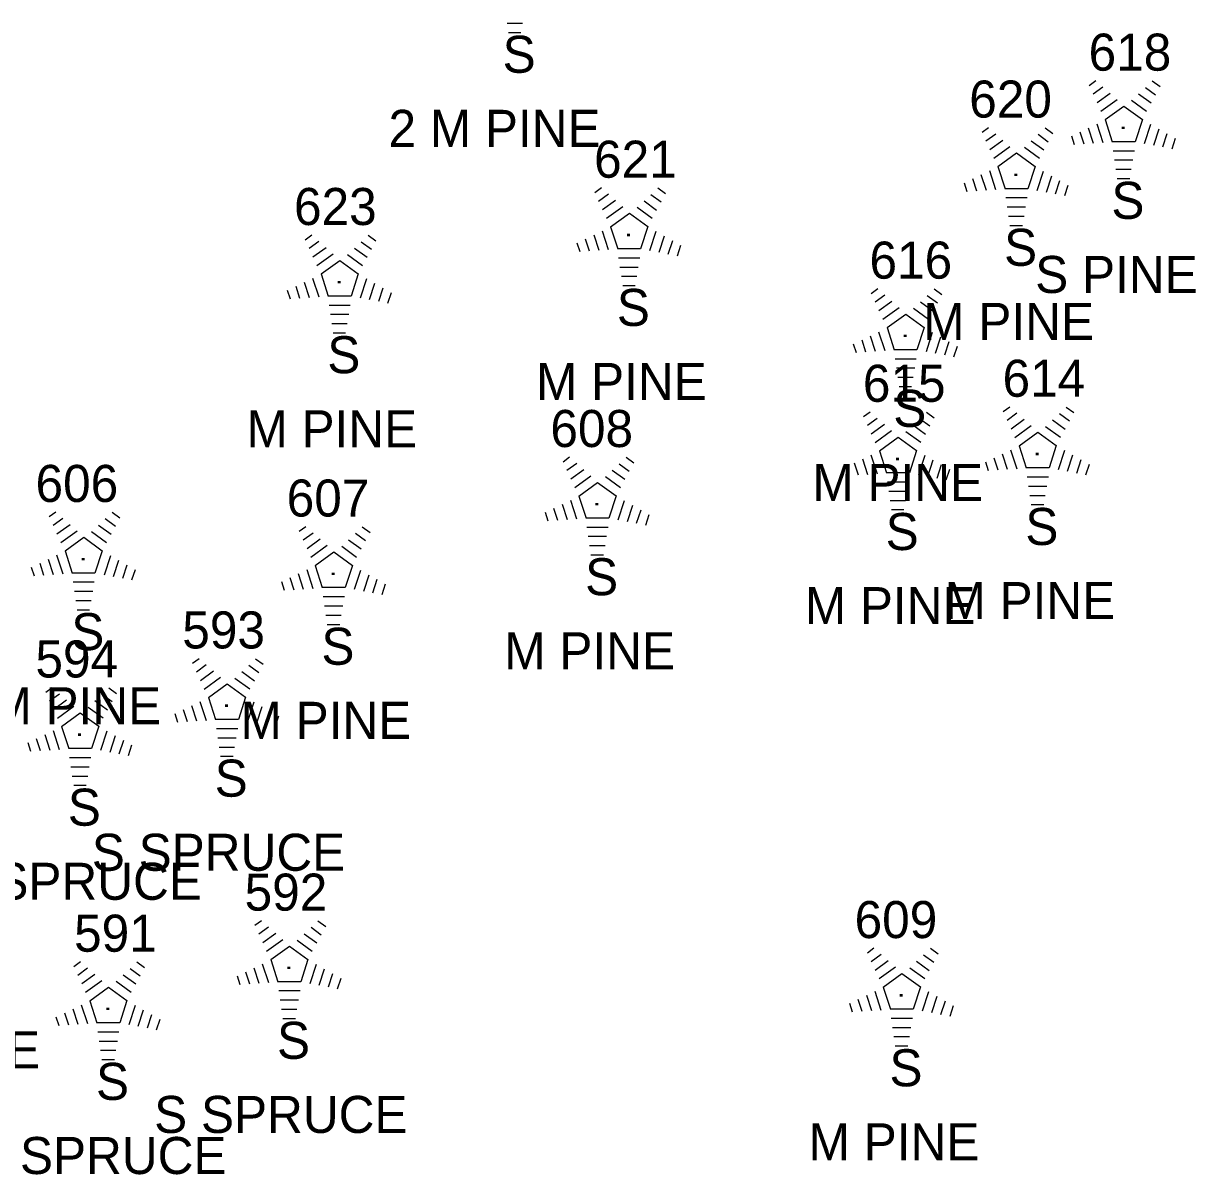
# Model space of a CAD drawing. Extents: x 1545627 to 1546562, y 571176 to 576667.
# Drawn here: x 1546217.9 to 1546281.1, y 572043.8 to 572106 of the extents above; entities that cross this region are included whole.
import ezdxf

# ---------------------------------------------------------------- set-up
doc = ezdxf.new("R2010")
doc.units = 0
for name, color, linetype in [('L_A', 7, 'Continuous'), ('L_C', 7, 'Continuous'), ('L_I', 7, 'Continuous'), ('LTC', 7, 'Continuous')]:
    doc.layers.add(name, color=color, linetype=linetype)

msp = doc.modelspace()

# ---------------------------------------------------------------- linework, layer by layer
at = {"layer": 'LTC'}
for p, q in [((1546244.786, 572105.976), (1546243.955, 572105.976)), ((1546244.703, 572105.476), (1546244.028, 572105.476)), ((1546275.376, 572102.634), (1546275.731, 572102.891)), ((1546275.586, 572102.168), (1546276.115, 572102.553)), ((1546278.403, 572102.526), (1546278.953, 572102.127)), ((1546278.774, 572102.874), (1546279.193, 572102.57)), ((1546275.795, 572101.703), (1546276.499, 572102.214)), ((1546276.005, 572101.237), (1546276.883, 572101.875)), ((1546277.661, 572101.829), (1546278.471, 572101.241)), ((1546278.032, 572102.178), (1546278.711, 572101.684)), ((1546276.229, 572100.782), (1546277.241, 572101.516)), ((1546277.241, 572101.516), (1546278.238, 572100.791)), ((1546275.775, 572100.563), (1546276.106, 572099.543)), ((1546276.229, 572100.782), (1546276.616, 572099.588)), ((1546278.238, 572100.791), (1546277.847, 572099.588)), ((1546269.587, 572100.101), (1546269.942, 572100.359)), ((1546269.797, 572099.636), (1546270.326, 572100.02)), ((1546272.614, 572099.993), (1546273.164, 572099.594)), ((1546272.985, 572100.342), (1546273.404, 572100.037)), ((1546274.408, 572099.913), (1546274.561, 572099.445)), ((1546274.864, 572100.13), (1546275.076, 572099.478)), ((1546275.319, 572100.346), (1546275.591, 572099.511)), ((1546278.676, 572100.521), (1546278.338, 572099.481)), ((1546279.12, 572100.27), (1546278.833, 572099.386)), ((1546279.565, 572100.02), (1546279.328, 572099.291)), ((1546270.006, 572099.17), (1546270.71, 572099.681)), ((1546270.216, 572098.704), (1546271.094, 572099.342)), ((1546271.872, 572099.297), (1546272.682, 572098.708)), ((1546272.243, 572099.645), (1546272.922, 572099.151)), ((1546277.847, 572099.588), (1546276.616, 572099.588)), ((1546280.009, 572099.77), (1546279.822, 572099.196)), ((1546270.44, 572098.249), (1546271.452, 572098.984)), ((1546271.452, 572098.984), (1546272.449, 572098.259)), ((1546277.808, 572099.088), (1546276.664, 572099.088)), ((1546269.986, 572098.03), (1546270.317, 572097.011)), ((1546270.44, 572098.249), (1546270.827, 572097.056)), ((1546272.449, 572098.259), (1546272.058, 572097.056)), ((1546277.725, 572098.588), (1546276.736, 572098.588)), ((1546277.641, 572098.088), (1546276.809, 572098.088)), ((1546268.619, 572097.38), (1546268.772, 572096.912)), ((1546269.075, 572097.597), (1546269.287, 572096.945)), ((1546269.53, 572097.814), (1546269.802, 572096.978)), ((1546272.887, 572097.988), (1546272.549, 572096.948)), ((1546273.331, 572097.737), (1546273.044, 572096.853)), ((1546273.776, 572097.487), (1546273.539, 572096.758)), ((1546277.557, 572097.588), (1546276.882, 572097.588)), ((1546248.687, 572096.855), (1546249.041, 572097.113)), ((1546248.896, 572096.39), (1546249.425, 572096.774)), ((1546251.714, 572096.748), (1546252.263, 572096.348)), ((1546252.085, 572097.096), (1546252.504, 572096.791)), ((1546272.058, 572097.056), (1546270.827, 572097.056)), ((1546274.22, 572097.237), (1546274.033, 572096.663)), ((1546249.106, 572095.924), (1546249.81, 572096.435)), ((1546251.343, 572096.399), (1546252.022, 572095.905)), ((1546272.019, 572096.556), (1546270.875, 572096.556)), ((1546249.315, 572095.458), (1546250.194, 572096.096)), ((1546249.54, 572095.003), (1546250.552, 572095.738)), ((1546250.552, 572095.738), (1546251.549, 572095.013)), ((1546250.972, 572096.051), (1546251.781, 572095.462)), ((1546271.936, 572096.056), (1546270.947, 572096.056)), ((1546271.852, 572095.556), (1546271.02, 572095.556)), ((1546249.54, 572095.003), (1546249.927, 572093.81)), ((1546251.549, 572095.013), (1546251.158, 572093.81)), ((1546271.768, 572095.056), (1546271.093, 572095.056)), ((1546233.059, 572094.304), (1546233.414, 572094.561)), ((1546233.269, 572093.838), (1546233.798, 572094.222)), ((1546236.457, 572094.544), (1546236.877, 572094.239)), ((1546248.175, 572094.351), (1546248.386, 572093.7)), ((1546248.63, 572094.568), (1546248.901, 572093.733)), ((1546249.085, 572094.784), (1546249.416, 572093.765)), ((1546251.986, 572094.742), (1546251.648, 572093.703)), ((1546252.431, 572094.492), (1546252.143, 572093.607)), ((1546252.875, 572094.242), (1546252.638, 572093.512)), ((1546233.478, 572093.372), (1546234.182, 572093.884)), ((1546235.715, 572093.847), (1546236.395, 572093.354)), ((1546236.086, 572094.196), (1546236.636, 572093.797)), ((1546247.719, 572094.135), (1546247.871, 572093.667)), ((1546251.158, 572093.81), (1546249.927, 572093.81)), ((1546253.32, 572093.991), (1546253.133, 572093.417)), ((1546233.688, 572092.907), (1546234.566, 572093.544)), ((1546233.912, 572092.452), (1546234.924, 572093.186)), ((1546234.924, 572093.186), (1546235.921, 572092.461)), ((1546235.344, 572093.499), (1546236.154, 572092.91)), ((1546251.119, 572093.31), (1546249.975, 572093.31)), ((1546233.912, 572092.452), (1546234.3, 572091.258)), ((1546235.921, 572092.461), (1546235.53, 572091.258)), ((1546251.035, 572092.81), (1546250.047, 572092.81)), ((1546250.952, 572092.31), (1546250.12, 572092.31)), ((1546232.547, 572091.799), (1546232.759, 572091.148)), ((1546233.002, 572092.016), (1546233.274, 572091.181)), ((1546233.458, 572092.232), (1546233.789, 572091.213)), ((1546236.359, 572092.19), (1546236.021, 572091.151)), ((1546236.803, 572091.94), (1546236.516, 572091.055)), ((1546237.248, 572091.69), (1546237.011, 572090.96)), ((1546250.868, 572091.81), (1546250.193, 572091.81)), ((1546232.092, 572091.583), (1546232.244, 572091.115)), ((1546235.53, 572091.258), (1546234.3, 572091.258)), ((1546237.692, 572091.439), (1546237.505, 572090.865)), ((1546263.605, 572091.407), (1546263.959, 572091.664)), ((1546263.814, 572090.941), (1546264.343, 572091.326)), ((1546266.632, 572091.299), (1546267.181, 572090.9)), ((1546267.003, 572091.647), (1546267.422, 572091.343)), ((1546235.492, 572090.758), (1546234.347, 572090.758)), ((1546264.024, 572090.476), (1546264.727, 572090.987)), ((1546264.233, 572090.01), (1546265.112, 572090.648)), ((1546265.89, 572090.602), (1546266.699, 572090.014)), ((1546266.261, 572090.951), (1546266.94, 572090.457)), ((1546235.408, 572090.258), (1546234.42, 572090.258)), ((1546264.458, 572089.555), (1546265.47, 572090.289)), ((1546265.47, 572090.289), (1546266.467, 572089.564)), ((1546235.324, 572089.758), (1546234.492, 572089.758)), ((1546235.24, 572089.258), (1546234.565, 572089.258)), ((1546264.003, 572089.336), (1546264.334, 572088.316)), ((1546264.458, 572089.555), (1546264.845, 572088.361)), ((1546266.467, 572089.564), (1546266.075, 572088.361)), ((1546266.904, 572089.294), (1546266.566, 572088.254)), ((1546262.637, 572088.686), (1546262.789, 572088.218)), ((1546263.092, 572088.903), (1546263.304, 572088.251)), ((1546263.548, 572089.119), (1546263.819, 572088.284)), ((1546267.349, 572089.043), (1546267.061, 572088.159)), ((1546267.793, 572088.793), (1546267.556, 572088.064)), ((1546268.237, 572088.543), (1546268.051, 572087.969)), ((1546266.075, 572088.361), (1546264.845, 572088.361)), ((1546266.037, 572087.861), (1546264.892, 572087.861)), ((1546265.953, 572087.361), (1546264.965, 572087.361)), ((1546265.87, 572086.861), (1546265.038, 572086.861)), ((1546265.786, 572086.361), (1546265.111, 572086.361)), ((1546263.193, 572084.759), (1546263.548, 572085.017)), ((1546266.592, 572085), (1546267.011, 572084.695)), ((1546270.733, 572085.031), (1546271.087, 572085.288)), ((1546270.942, 572084.565), (1546271.471, 572084.949)), ((1546273.76, 572084.923), (1546274.309, 572084.524)), ((1546274.131, 572085.271), (1546274.55, 572084.967)), ((1546263.403, 572084.294), (1546263.932, 572084.678)), ((1546263.612, 572083.828), (1546264.316, 572084.339)), ((1546265.849, 572084.303), (1546266.529, 572083.809)), ((1546266.22, 572084.651), (1546266.77, 572084.252)), ((1546271.152, 572084.099), (1546271.856, 572084.611)), ((1546271.361, 572083.634), (1546272.24, 572084.272)), ((1546273.018, 572084.226), (1546273.827, 572083.637)), ((1546273.389, 572084.574), (1546274.068, 572084.081)), ((1546263.822, 572083.362), (1546264.7, 572084)), ((1546264.047, 572082.907), (1546265.058, 572083.642)), ((1546265.058, 572083.642), (1546266.055, 572082.917)), ((1546265.478, 572083.955), (1546266.288, 572083.366)), ((1546271.586, 572083.179), (1546272.598, 572083.913)), ((1546272.598, 572083.913), (1546273.595, 572083.188)), ((1546264.047, 572082.907), (1546264.434, 572081.714)), ((1546266.055, 572082.917), (1546265.664, 572081.714)), ((1546271.131, 572082.959), (1546271.462, 572081.94)), ((1546271.586, 572083.179), (1546271.973, 572081.985)), ((1546273.595, 572083.188), (1546273.204, 572081.985)), ((1546274.032, 572082.917), (1546273.694, 572081.878)), ((1546246.975, 572082.319), (1546247.329, 572082.576)), ((1546247.184, 572081.854), (1546247.713, 572082.238)), ((1546250.002, 572082.211), (1546250.551, 572081.812)), ((1546250.373, 572082.559), (1546250.792, 572082.255)), ((1546262.681, 572082.255), (1546262.893, 572081.603)), ((1546263.137, 572082.472), (1546263.408, 572081.636)), ((1546263.592, 572082.688), (1546263.923, 572081.669)), ((1546266.493, 572082.646), (1546266.155, 572081.606)), ((1546266.937, 572082.395), (1546266.65, 572081.511)), ((1546269.765, 572082.31), (1546269.917, 572081.842)), ((1546270.221, 572082.527), (1546270.432, 572081.875)), ((1546270.676, 572082.743), (1546270.947, 572081.908)), ((1546274.477, 572082.667), (1546274.189, 572081.782)), ((1546274.921, 572082.417), (1546274.684, 572081.687)), ((1546247.394, 572081.388), (1546248.098, 572081.899)), ((1546247.603, 572080.922), (1546248.482, 572081.56)), ((1546249.631, 572081.863), (1546250.31, 572081.369)), ((1546262.226, 572082.038), (1546262.378, 572081.57)), ((1546265.664, 572081.714), (1546264.434, 572081.714)), ((1546267.382, 572082.145), (1546267.145, 572081.416)), ((1546267.826, 572081.895), (1546267.639, 572081.321)), ((1546273.204, 572081.985), (1546271.973, 572081.985)), ((1546275.366, 572082.167), (1546275.179, 572081.592)), ((1546247.828, 572080.467), (1546248.84, 572081.201)), ((1546248.84, 572081.201), (1546249.837, 572080.476)), ((1546249.26, 572081.514), (1546250.069, 572080.926)), ((1546265.626, 572081.214), (1546264.481, 572081.214)), ((1546273.165, 572081.485), (1546272.021, 572081.485)), ((1546273.081, 572080.985), (1546272.093, 572080.985)), ((1546247.828, 572080.467), (1546248.215, 572079.274)), ((1546249.837, 572080.476), (1546249.445, 572079.274)), ((1546265.542, 572080.714), (1546264.554, 572080.714)), ((1546272.998, 572080.485), (1546272.166, 572080.485)), ((1546246.463, 572079.815), (1546246.674, 572079.163)), ((1546246.918, 572080.031), (1546247.189, 572079.196)), ((1546247.373, 572080.248), (1546247.704, 572079.229)), ((1546250.274, 572080.206), (1546249.936, 572079.166)), ((1546250.719, 572079.955), (1546250.431, 572079.071)), ((1546251.163, 572079.705), (1546250.926, 572078.976)), ((1546265.458, 572080.214), (1546264.627, 572080.214)), ((1546265.374, 572079.714), (1546264.699, 572079.714)), ((1546272.914, 572079.985), (1546272.239, 572079.985)), ((1546219.242, 572079.355), (1546219.597, 572079.612)), ((1546219.452, 572078.889), (1546219.981, 572079.274)), ((1546222.269, 572079.247), (1546222.819, 572078.848)), ((1546222.64, 572079.595), (1546223.06, 572079.291)), ((1546246.007, 572079.598), (1546246.159, 572079.13)), ((1546249.445, 572079.274), (1546248.215, 572079.274)), ((1546251.608, 572079.455), (1546251.421, 572078.881)), ((1546219.661, 572078.424), (1546220.365, 572078.935)), ((1546219.871, 572077.958), (1546220.749, 572078.596)), ((1546221.527, 572078.55), (1546222.337, 572077.962)), ((1546221.898, 572078.899), (1546222.578, 572078.405)), ((1546232.741, 572078.567), (1546233.095, 572078.824)), ((1546232.95, 572078.101), (1546233.48, 572078.485)), ((1546235.768, 572078.459), (1546236.318, 572078.059)), ((1546236.139, 572078.807), (1546236.558, 572078.502)), ((1546249.407, 572078.774), (1546248.263, 572078.774)), ((1546220.095, 572077.503), (1546221.107, 572078.237)), ((1546221.107, 572078.237), (1546222.104, 572077.512)), ((1546233.16, 572077.635), (1546233.864, 572078.147)), ((1546233.37, 572077.169), (1546234.248, 572077.807)), ((1546235.026, 572077.762), (1546235.835, 572077.173)), ((1546235.397, 572078.11), (1546236.076, 572077.617)), ((1546249.323, 572078.274), (1546248.335, 572078.274)), ((1546249.24, 572077.774), (1546248.408, 572077.774)), ((1546219.641, 572077.284), (1546219.972, 572076.264)), ((1546220.095, 572077.503), (1546220.483, 572076.309)), ((1546222.104, 572077.512), (1546221.713, 572076.309)), ((1546222.542, 572077.242), (1546222.204, 572076.202)), ((1546233.594, 572076.714), (1546234.606, 572077.449)), ((1546234.606, 572077.449), (1546235.603, 572076.724)), ((1546249.156, 572077.274), (1546248.481, 572077.274)), ((1546218.275, 572076.634), (1546218.427, 572076.166)), ((1546218.73, 572076.851), (1546218.942, 572076.199)), ((1546219.185, 572077.067), (1546219.457, 572076.232)), ((1546222.986, 572076.991), (1546222.699, 572076.107)), ((1546223.431, 572076.741), (1546223.194, 572076.012)), ((1546223.875, 572076.491), (1546223.688, 572075.917)), ((1546233.14, 572076.495), (1546233.47, 572075.476)), ((1546233.594, 572076.714), (1546233.981, 572075.521)), ((1546235.603, 572076.724), (1546235.212, 572075.521)), ((1546221.713, 572076.309), (1546220.483, 572076.309)), ((1546232.229, 572076.062), (1546232.44, 572075.411)), ((1546232.684, 572076.279), (1546232.955, 572075.444)), ((1546236.04, 572076.453), (1546235.703, 572075.414)), ((1546236.485, 572076.203), (1546236.198, 572075.318)), ((1546236.93, 572075.953), (1546236.693, 572075.223)), ((1546221.675, 572075.809), (1546220.53, 572075.809)), ((1546221.591, 572075.309), (1546220.603, 572075.309)), ((1546231.773, 572075.846), (1546231.925, 572075.378)), ((1546235.212, 572075.521), (1546233.981, 572075.521)), ((1546237.374, 572075.702), (1546237.187, 572075.128)), ((1546221.507, 572074.809), (1546220.675, 572074.809)), ((1546235.173, 572075.021), (1546234.029, 572075.021)), ((1546221.423, 572074.309), (1546220.748, 572074.309)), ((1546235.09, 572074.521), (1546234.101, 572074.521)), ((1546235.006, 572074.021), (1546234.174, 572074.021)), ((1546234.922, 572073.521), (1546234.247, 572073.521)), ((1546226.981, 572071.447), (1546227.335, 572071.704)), ((1546230.379, 572071.687), (1546230.798, 572071.382)), ((1546227.19, 572070.981), (1546227.72, 572071.365)), ((1546227.4, 572070.515), (1546228.104, 572071.027)), ((1546229.637, 572070.99), (1546230.316, 572070.497)), ((1546230.008, 572071.339), (1546230.558, 572070.94)), ((1546227.61, 572070.05), (1546228.488, 572070.687)), ((1546227.834, 572069.595), (1546228.846, 572070.329)), ((1546228.846, 572070.329), (1546229.843, 572069.604)), ((1546229.266, 572070.642), (1546230.075, 572070.053)), ((1546219.056, 572069.88), (1546219.41, 572070.137)), ((1546219.265, 572069.414), (1546219.795, 572069.798)), ((1546222.083, 572069.772), (1546222.633, 572069.372)), ((1546222.454, 572070.12), (1546222.873, 572069.815)), ((1546227.834, 572069.595), (1546228.221, 572068.401)), ((1546229.843, 572069.604), (1546229.452, 572068.401)), ((1546219.475, 572068.948), (1546220.179, 572069.46)), ((1546219.685, 572068.482), (1546220.563, 572069.12)), ((1546221.341, 572069.075), (1546222.15, 572068.486)), ((1546221.712, 572069.423), (1546222.391, 572068.93)), ((1546226.469, 572068.942), (1546226.68, 572068.291)), ((1546226.924, 572069.159), (1546227.195, 572068.324)), ((1546227.38, 572069.375), (1546227.71, 572068.356)), ((1546230.28, 572069.333), (1546229.943, 572068.294)), ((1546230.725, 572069.083), (1546230.438, 572068.198)), ((1546219.909, 572068.027), (1546220.921, 572068.762)), ((1546220.921, 572068.762), (1546221.918, 572068.037)), ((1546226.013, 572068.726), (1546226.165, 572068.258)), ((1546229.452, 572068.401), (1546228.221, 572068.401)), ((1546231.17, 572068.833), (1546230.933, 572068.103)), ((1546231.614, 572068.582), (1546231.427, 572068.008)), ((1546219.455, 572067.808), (1546219.785, 572066.789)), ((1546219.909, 572068.027), (1546220.296, 572066.834)), ((1546221.918, 572068.037), (1546221.527, 572066.834)), ((1546222.355, 572067.766), (1546222.018, 572066.727)), ((1546229.413, 572067.901), (1546228.269, 572067.901)), ((1546218.088, 572067.159), (1546218.24, 572066.691)), ((1546218.544, 572067.375), (1546218.755, 572066.724)), ((1546218.999, 572067.592), (1546219.27, 572066.757)), ((1546222.8, 572067.516), (1546222.513, 572066.631)), ((1546223.245, 572067.266), (1546223.008, 572066.536)), ((1546223.689, 572067.015), (1546223.502, 572066.441)), ((1546229.33, 572067.401), (1546228.341, 572067.401)), ((1546221.527, 572066.834), (1546220.296, 572066.834)), ((1546229.246, 572066.901), (1546228.414, 572066.901)), ((1546229.162, 572066.401), (1546228.487, 572066.401)), ((1546221.488, 572066.334), (1546220.344, 572066.334)), ((1546221.405, 572065.834), (1546220.416, 572065.834)), ((1546221.321, 572065.334), (1546220.489, 572065.334)), ((1546221.237, 572064.834), (1546220.562, 572064.834)), ((1546230.345, 572057.295), (1546230.7, 572057.552)), ((1546233.743, 572057.535), (1546234.163, 572057.23)), ((1546230.555, 572056.829), (1546231.084, 572057.213)), ((1546233.372, 572057.187), (1546233.922, 572056.787)), ((1546230.764, 572056.363), (1546231.468, 572056.875)), ((1546230.974, 572055.897), (1546231.852, 572056.535)), ((1546232.63, 572056.49), (1546233.44, 572055.901)), ((1546233.001, 572056.838), (1546233.681, 572056.345)), ((1546231.198, 572055.442), (1546232.21, 572056.177)), ((1546232.21, 572056.177), (1546233.207, 572055.452)), ((1546263.4, 572055.813), (1546263.755, 572056.07)), ((1546263.61, 572055.347), (1546264.139, 572055.731)), ((1546266.428, 572055.705), (1546266.977, 572055.305)), ((1546266.799, 572056.053), (1546267.218, 572055.748)), ((1546220.576, 572055.077), (1546220.93, 572055.334)), ((1546220.785, 572054.611), (1546221.315, 572054.996)), ((1546223.974, 572055.317), (1546224.393, 572055.013)), ((1546230.288, 572055.007), (1546230.56, 572054.172)), ((1546230.744, 572055.223), (1546231.075, 572054.204)), ((1546231.198, 572055.442), (1546231.586, 572054.249)), ((1546233.207, 572055.452), (1546232.816, 572054.249)), ((1546233.645, 572055.181), (1546233.307, 572054.142)), ((1546263.82, 572054.881), (1546264.523, 572055.393)), ((1546264.029, 572054.415), (1546264.908, 572055.053)), ((1546265.685, 572055.008), (1546266.495, 572054.419)), ((1546266.057, 572055.356), (1546266.736, 572054.863)), ((1546220.995, 572054.146), (1546221.699, 572054.657)), ((1546223.232, 572054.621), (1546223.911, 572054.127)), ((1546223.603, 572054.969), (1546224.153, 572054.57)), ((1546229.378, 572054.574), (1546229.53, 572054.106)), ((1546229.833, 572054.79), (1546230.045, 572054.139)), ((1546234.089, 572054.931), (1546233.802, 572054.046)), ((1546234.534, 572054.681), (1546234.297, 572053.951)), ((1546234.978, 572054.43), (1546234.791, 572053.856)), ((1546264.254, 572053.96), (1546265.265, 572054.695)), ((1546265.265, 572054.695), (1546266.263, 572053.97)), ((1546221.205, 572053.68), (1546222.083, 572054.318)), ((1546221.429, 572053.225), (1546222.441, 572053.959)), ((1546222.441, 572053.959), (1546223.438, 572053.234)), ((1546222.861, 572054.272), (1546223.67, 572053.684)), ((1546232.816, 572054.249), (1546231.586, 572054.249)), ((1546232.778, 572053.749), (1546231.633, 572053.749)), ((1546263.799, 572053.741), (1546264.13, 572052.722)), ((1546264.254, 572053.96), (1546264.641, 572052.767)), ((1546266.263, 572053.97), (1546265.871, 572052.767)), ((1546221.429, 572053.225), (1546221.816, 572052.031)), ((1546223.438, 572053.234), (1546223.047, 572052.031)), ((1546232.694, 572053.249), (1546231.706, 572053.249)), ((1546262.433, 572053.092), (1546262.585, 572052.624)), ((1546262.888, 572053.308), (1546263.1, 572052.657)), ((1546263.344, 572053.525), (1546263.615, 572052.69)), ((1546266.7, 572053.699), (1546266.362, 572052.66)), ((1546267.145, 572053.449), (1546266.857, 572052.564)), ((1546267.589, 572053.199), (1546267.352, 572052.469)), ((1546220.064, 572052.573), (1546220.275, 572051.921)), ((1546220.519, 572052.789), (1546220.79, 572051.954)), ((1546220.975, 572053.006), (1546221.305, 572051.986)), ((1546223.875, 572052.964), (1546223.538, 572051.924)), ((1546224.32, 572052.713), (1546224.033, 572051.829)), ((1546224.765, 572052.463), (1546224.528, 572051.734)), ((1546232.61, 572052.749), (1546231.778, 572052.749)), ((1546265.871, 572052.767), (1546264.641, 572052.767)), ((1546268.033, 572052.948), (1546267.847, 572052.374)), ((1546219.608, 572052.356), (1546219.76, 572051.888)), ((1546223.047, 572052.031), (1546221.816, 572052.031)), ((1546225.209, 572052.213), (1546225.022, 572051.639)), ((1546232.526, 572052.249), (1546231.851, 572052.249)), ((1546265.833, 572052.267), (1546264.688, 572052.267)), ((1546223.008, 572051.531), (1546221.864, 572051.531)), ((1546265.749, 572051.767), (1546264.761, 572051.767)), ((1546265.665, 572051.267), (1546264.834, 572051.267)), ((1546222.925, 572051.031), (1546221.936, 572051.031)), ((1546265.582, 572050.767), (1546264.907, 572050.767)), ((1546222.841, 572050.531), (1546222.009, 572050.531)), ((1546222.757, 572050.031), (1546222.082, 572050.031))]:
    msp.add_line(p, q, dxfattribs=at)

# ---------------------------------------------------------------- texts
at = {"layer": 'L_A'}
for p in [(1546243.712, 572103.313), (1546276.567, 572095.426), (1546270.778, 572092.893), (1546249.877, 572089.647), (1546234.25, 572087.095), (1546264.795, 572084.199), (1546271.923, 572077.823), (1546264.384, 572077.551), (1546248.165, 572075.111), (1546220.433, 572072.147), (1546233.932, 572071.358), (1546228.172, 572064.238), (1546220.247, 572062.671), (1546231.536, 572050.086), (1546264.591, 572048.604), (1546221.767, 572047.869)]:
    msp.add_text('S', height=2, dxfattribs=at).set_placement(p)
at = {"layer": 'L_C'}
for s, p in [('2 M PINE', (1546237.554, 572099.313)), ('S PINE', (1546272.456, 572091.426)), ('M PINE', (1546266.415, 572088.893)), ('M PINE', (1546245.515, 572085.647)), ('M PINE', (1546229.888, 572083.095)), ('M PINE', (1546260.433, 572080.199)), ('M PINE', (1546260.022, 572073.551)), ('M PINE', (1546267.561, 572073.823)), ('M PINE', (1546243.803, 572071.111)), ('M PINE', (1546216.071, 572068.147)), ('M PINE', (1546229.569, 572067.358)), ('S SPRUCE', (1546221.542, 572060.238)), ('M SPRUCE', (1546213.365, 572058.671)), ('M PINE', (1546209.538, 572049.574)), ('S SPRUCE', (1546224.906, 572046.086)), ('M PINE', (1546260.229, 572044.604)), ('S SPRUCE', (1546215.137, 572043.869))]:
    msp.add_text(s, height=2, dxfattribs=at).set_placement(p)
at = {"layer": 'L_I'}
for s, p in [('618', (1546275.338, 572103.426)), ('620', (1546268.896, 572100.893)), ('621', (1546248.649, 572097.647)), ('623', (1546232.454, 572095.095)), ('616', (1546263.512, 572092.199)), ('615', (1546263.156, 572085.551)), ('614', (1546270.695, 572085.823)), ('608', (1546246.291, 572083.111)), ('606', (1546218.504, 572080.147)), ('607', (1546232.058, 572079.358)), ('593', (1546226.424, 572072.238)), ('594', (1546218.499, 572070.671)), ('592', (1546229.788, 572058.086)), ('609', (1546262.709, 572056.604)), ('591', (1546220.585, 572055.869))]:
    msp.add_text(s, height=2, dxfattribs=at).set_placement(p)
at = {"layer": 'LTC'}
for p in [(1546277.123, 572100.53), (1546271.334, 572097.997), (1546250.434, 572094.751), (1546234.807, 572092.199), (1546265.352, 572089.303), (1546264.941, 572082.655), (1546272.48, 572082.927), (1546248.722, 572080.215), (1546220.99, 572077.251), (1546234.488, 572076.462), (1546228.728, 572069.342), (1546220.803, 572067.775), (1546232.093, 572055.19), (1546265.148, 572053.708), (1546222.323, 572052.973)]:
    msp.add_text('.', height=1.037, rotation=270, dxfattribs=at).set_placement(p)

doc.saveas('drawing.dxf')
